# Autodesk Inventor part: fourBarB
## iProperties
Created: 2008-10
Part Number: fourBarB
Document SubType Name: Modeling
Designer: Lochan
Density: 1 g/cm^3
Mass: 2.624 g
Surface Area: 24.9322 cm^2
Volume: 2.624 cm^3
Author: Lochan
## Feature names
1. Extrusion1
2. Extrusion2
